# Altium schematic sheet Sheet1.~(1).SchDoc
size A4
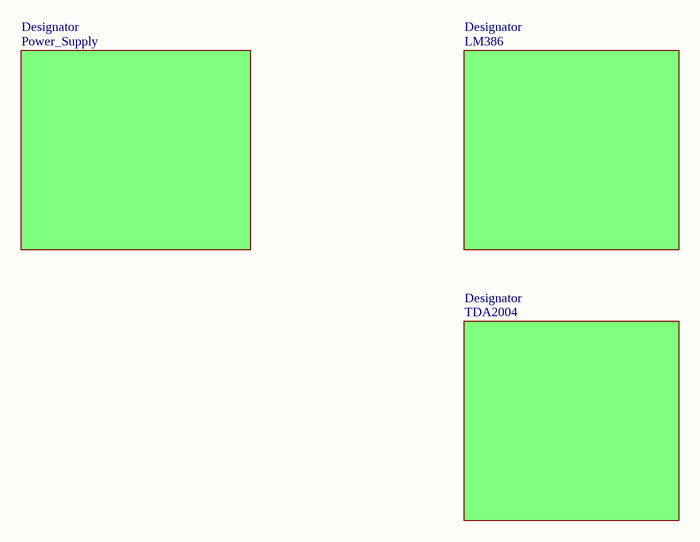
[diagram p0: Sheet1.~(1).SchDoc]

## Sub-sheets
Designator = Power_Supply: no entries
Designator = LM386: no entries
Designator = TDA2004: no entries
